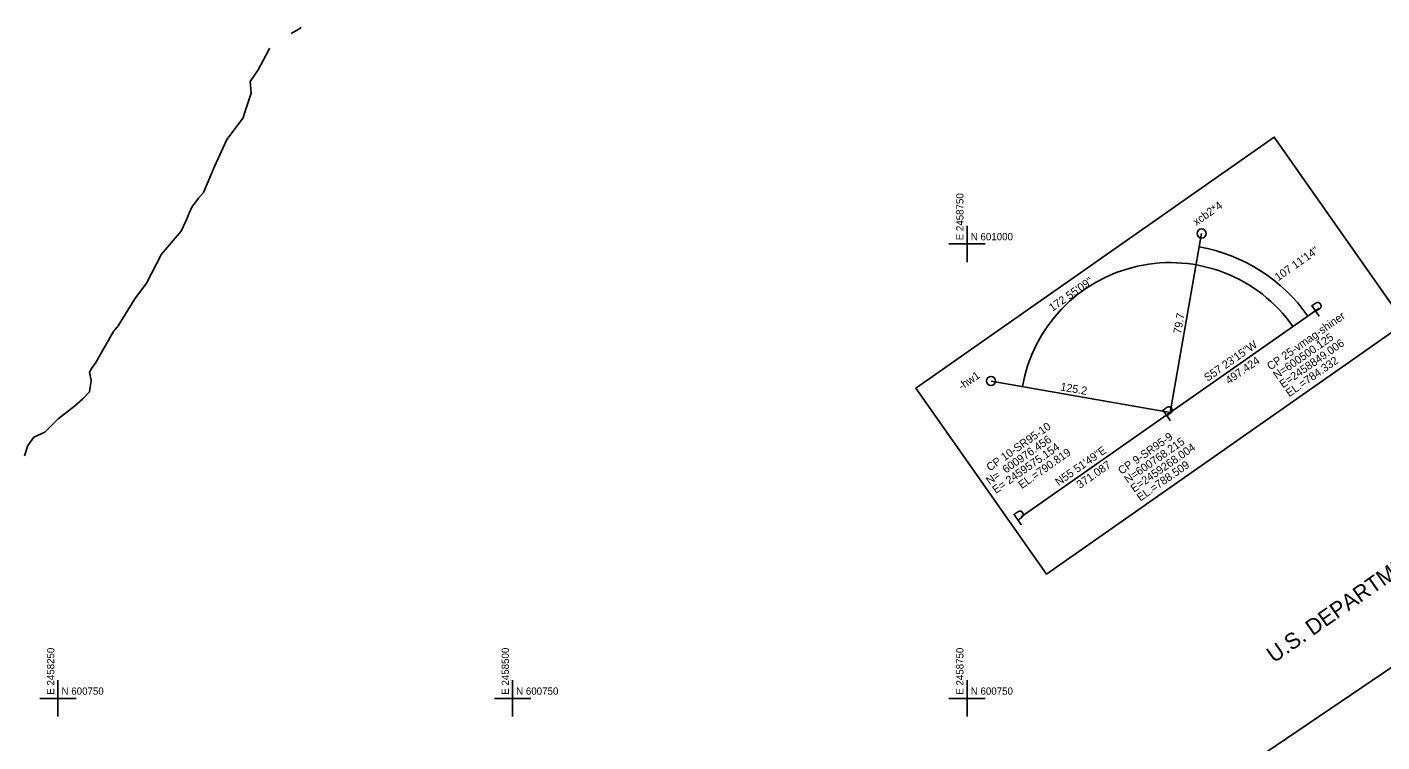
# Model space of a CAD drawing. Extents: x 2443269 to 2494951, y 591171 to 622130.
# Drawn here: x 2458233 to 2458978, y 600726 to 601119 of the extents above; entities that cross this region are included whole.
import ezdxf

# ---------------------------------------------------------------- set-up
doc = ezdxf.new("R2010")
doc.units = 0
for name, color, linetype in [('SURVEY - CONTROL - Grid', 7, 'Continuous'), ('SURVEY - CONTROL - Grid Text', 7, 'Continuous'), ('SURVEY - CONTROL with Text', 7, 'Continuous'), ('SURVEY - DRAINAGE - Natural Features', 7, 'Continuous'), ('SURVEY - PROPERTY - Owners', 7, 'Continuous'), ('SURVEY - PROPERTY - ROW Lines', 7, 'Continuous')]:
    doc.layers.add(name, color=color, linetype=linetype)

msp = doc.modelspace()

# ---------------------------------------------------------------- linework, layer by layer
at = {"layer": 'SURVEY - CONTROL - Grid'}
for p, q in [((2458750, 600990), (2458750, 601010)), ((2458740, 601000), (2458760, 601000)), ((2458250, 600740), (2458250, 600760)), ((2458500, 600740), (2458500, 600760)), ((2458750, 600740), (2458750, 600760)), ((2458240, 600750), (2458260, 600750)), ((2458490, 600750), (2458510, 600750)), ((2458740, 600750), (2458760, 600750))]:
    msp.add_line(p, q, dxfattribs=at)
at = {"layer": 'SURVEY - CONTROL with Text'}
for p, q in [((2458861.637, 600907.225), (2458878.967, 601005.712)), ((2458877.668, 600998.325), (2458877.668, 600998.325)), ((2458861.637, 600907.225), (2458943.532, 600964.61)), ((2458937.39, 600960.306), (2458937.39, 600960.306)), ((2458929.2, 600954.568), (2458929.2, 600954.568)), ((2458861.637, 600907.225), (2458763.15, 600924.556)), ((2458780.385, 600921.523), (2458780.385, 600921.523)), ((2458861.637, 600907.225), (2458779.741, 600849.839)), ((2458861.637, 600907.225), (2458861.637, 600907.225))]:
    msp.add_line(p, q, dxfattribs=at)
msp.add_lwpolyline([(2458793.645, 600818.275), (2458721.88, 600920.692), (2458918.883, 601058.736), (2458990.648, 600956.318)], close=True, dxfattribs=at)
for centre in [(2458878.968, 601005.711), (2458763.15, 600924.555)]:
    msp.add_circle(centre, 2.5, dxfattribs=at)
for radius, end in [(92.5, 80.019575), (82.5, 170.019578)]:
    msp.add_arc((2458861.637, 600907.224), radius, 35.019578, end, dxfattribs=at)
at = {"layer": 'SURVEY - DRAINAGE - Natural Features'}
for points in [[(2458383.472, 601119.264), (2458383.377, 601118.592), (2458378.249, 601115.714)], [(2458366.343, 601107.624), (2458365.972, 601106.8), (2458360.194, 601095.698), (2458355.739, 601089.271), (2458356.29, 601082.87), (2458352.734, 601072.545), (2458351.786, 601069.261), (2458342.845, 601057.434), (2458336.09, 601042.535), (2458329.968, 601028.29), (2458327.232, 601025.104), (2458323.587, 601020.212), (2458321.933, 601016.541), (2458321.031, 601014.11), (2458317.865, 601007.056), (2458306.996, 600994.307), (2458298.734, 600978.467), (2458292.36, 600969.75), (2458283.042, 600954.908), (2458280.477, 600951.797), (2458276.169, 600944.12), (2458274.177, 600940.554), (2458270.778, 600934.668), (2458268.547, 600931.368), (2458267.327, 600929.383), (2458268.236, 600924.842), (2458267.34, 600918.605), (2458263.751, 600914.74), (2458259.089, 600910.803), (2458250.073, 600903.854), (2458242.74, 600896.387), (2458236.694, 600893.723), (2458233.41, 600889.156), (2458231.599, 600883.395)]]:
    msp.add_lwpolyline(points, dxfattribs=at)
at = {"layer": 'SURVEY - PROPERTY - ROW Lines'}
msp.add_lwpolyline([(2457505.95, 599758.819), (2458654.814, 600544.619), (2459343.983, 601011.291)], dxfattribs=at)

# ---------------------------------------------------------------- texts
at = {"layer": 'SURVEY - CONTROL - Grid Text'}
for s, p in [('E 2458750', (2458748, 601002)), ('E 2458250', (2458248, 600752)), ('E 2458500', (2458498, 600752)), ('E 2458750', (2458748, 600752))]:
    msp.add_text(s, height=4, rotation=90, dxfattribs=at).set_placement(p)
for s, p in [('N 601000', (2458752, 601002)), ('N 600750', (2458252, 600752)), ('N 600750', (2458502, 600752)), ('N 600750', (2458752, 600752))]:
    msp.add_text(s, height=4, dxfattribs=at).set_placement(p)
at = {"layer": 'SURVEY - CONTROL with Text'}
for s, height, rotation, p in [('xcb2*4', 4.4, 35.019581, (2458876.099, 601009.806)), ('107 11\'14"', 4.4, 35.019581, (2458921.061, 600979.391)), ('172 55\'09"', 4.4, 35.019581, (2458796.877, 600962.585)), ('P', 7.5, 35.019581, (2458942.613, 600959.387)), ('79.7', 4.4, 80.019575, (2458867.674, 600950.28)), ('CP 25-vmag-shiner', 4.4, 35.019581, (2458916.802, 600930.329)), ('N=600500.125  ', 4.4, 35.019581, (2458920.245, 600925.415)), ('S57 23\'15"W', 4.4, 35.019581, (2458882.219, 600924.089)), ('E=2458849.006 ', 4.4, 35.019581, (2458923.688, 600920.501)), ('497.424', 4.4, 35.019581, (2458894.016, 600922.587)), ('EL.=784.332', 4.4, 35.019581, (2458927.131, 600915.587)), ('-hw1', 4.4, 35.019581, (2458747.068, 600919.392)), ('125.2', 4.4, 350.019578, (2458801.052, 600919.427)), ('P', 7.5, 35.019581, (2458860.718, 600902.001)), ('CP 10-SR95-10', 4.4, 35.019581, (2458762.497, 600874.754)), ('N=  600976.456', 4.4, 35.019581, (2458762.337, 600867.315)), ('E= 2459575.154', 4.4, 35.019581, (2458765.78, 600862.401)), ('CP 9-SR95-9', 4.4, 35.019581, (2458834.906, 600872.943)), ('N=600768.215  ', 4.4, 35.019581, (2458838.349, 600868.029)), ('E=2459268.004 ', 4.4, 35.019581, (2458841.793, 600863.116)), ('EL.=790.819', 4.4, 35.019581, (2458780.034, 600865.062)), ('N55 51\'49"E', 4.4, 35.019581, (2458800.322, 600866.703)), ('371.087', 4.4, 35.019581, (2458812.121, 600865.201)), ('EL.=788.509', 4.4, 35.019581, (2458845.236, 600858.202)), ('P', 7.5, 35.019581, (2458778.822, 600844.616))]:
    msp.add_text(s, height=height, rotation=rotation, dxfattribs=at).set_placement(p)
at = {"layer": 'SURVEY - PROPERTY - Owners'}
msp.add_text('U.S. DEPARTMENT OF ENERGY', height=8.75, rotation=35.019464, dxfattribs=at).set_placement((2458918.671, 600769.174))

doc.saveas('drawing.dxf')
